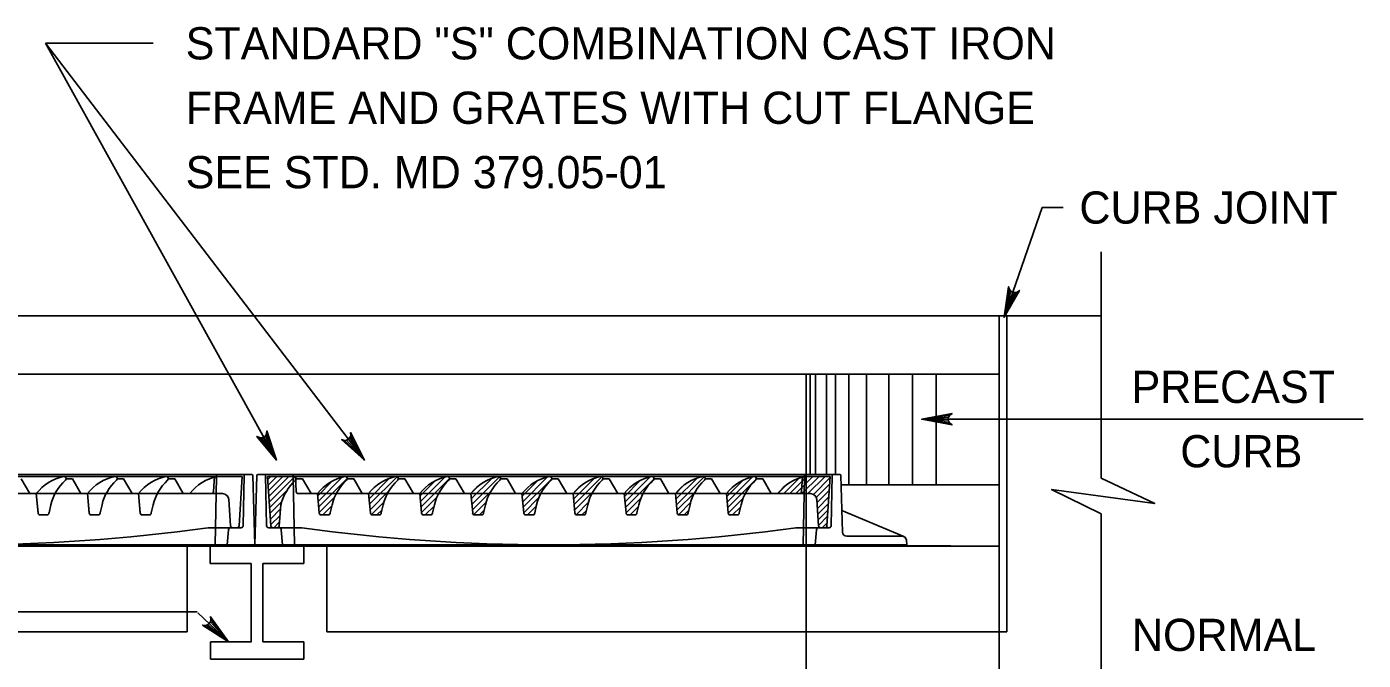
# Model space of a CAD drawing. Extents: x 2.4 to 9.7, y 1.1 to 11.2.
# Drawn here: x 7.045 to 9.535, y 9.981 to 11.161 of the extents above; entities that cross this region are included whole.
import ezdxf

# ---------------------------------------------------------------- set-up
doc = ezdxf.new("R2010")
doc.units = 0
for name, color, linetype in [('DETL-DIMS', 7, 'Continuous'), ('DETL-LINE', 7, 'Continuous'), ('DETL-NOTE', 7, 'Continuous'), ('DETL-PATT', 7, 'Continuous')]:
    doc.layers.add(name, color=color, linetype=linetype)

msp = doc.modelspace()

# ---------------------------------------------------------------- linework, layer by layer
at = {"layer": 'DETL-DIMS'}
for p, q in [((7.0801, 11.13), (7.2805, 11.13)), ((7.6745, 10.3536), (7.0801, 11.13)), ((7.0801, 11.13), (7.5105, 10.3536)), ((8.8661, 10.6198), (8.9368, 10.8241)), ((8.9368, 10.8241), (8.9761, 10.8241)), ((8.7127, 10.4299), (9.5353, 10.4299)), ((7.3624, 10.0708), (5.8534, 10.0708)), ((7.364, 10.0693), (7.4209, 10.0154))]:
    msp.add_line(p, q, dxfattribs=at)
for points in [[(8.8661, 10.6198), (8.8746, 10.6767), (8.876, 10.6716), (8.8788, 10.6682), (8.8822, 10.6664), (8.886, 10.6657), (8.8903, 10.6666), (8.8946, 10.6697), (8.8661, 10.6198), (8.8903, 10.6666), (8.886, 10.6657), (8.8661, 10.6198), (8.8822, 10.6664), (8.8788, 10.6682), (8.8661, 10.6198), (8.876, 10.6716)], [(8.7127, 10.4299), (8.7692, 10.4405), (8.7648, 10.4375), (8.7626, 10.4337), (8.7619, 10.4299), (8.7626, 10.4261), (8.7648, 10.4223), (8.7692, 10.4193), (8.7127, 10.4299), (8.7648, 10.4223), (8.7626, 10.4261), (8.7127, 10.4299), (8.7619, 10.4299), (8.7626, 10.4337), (8.7127, 10.4299), (8.7648, 10.4375)], [(7.5105, 10.3536), (7.4738, 10.3979), (7.4786, 10.3955), (7.483, 10.3954), (7.4866, 10.3967), (7.4896, 10.3991), (7.4918, 10.4029), (7.4924, 10.4081), (7.5105, 10.3536), (7.4918, 10.4029), (7.4896, 10.3991), (7.5105, 10.3536), (7.4866, 10.3967), (7.483, 10.3954), (7.5105, 10.3536), (7.4786, 10.3955)], [(7.6745, 10.3536), (7.6317, 10.392), (7.6368, 10.3904), (7.6411, 10.3909), (7.6445, 10.3927), (7.6472, 10.3955), (7.6488, 10.3996), (7.6485, 10.4049), (7.6745, 10.3536), (7.6488, 10.3996), (7.6472, 10.3955), (7.6745, 10.3536), (7.6445, 10.3927), (7.6411, 10.3909), (7.6745, 10.3536), (7.6368, 10.3904)], [(9.0468, 10.2538), (8.9546, 10.2989), (9.1468, 10.2728), (9.0468, 10.3203)], [(7.4209, 10.0154), (7.3726, 10.0465), (7.3778, 10.0457), (7.3821, 10.047), (7.3851, 10.0493), (7.3873, 10.0525), (7.3882, 10.0568), (7.3872, 10.0619), (7.4209, 10.0154), (7.3882, 10.0568), (7.3873, 10.0525), (7.4209, 10.0154), (7.3851, 10.0493), (7.3821, 10.047), (7.4209, 10.0154), (7.3778, 10.0457)]]:
    msp.add_lwpolyline(points, dxfattribs=at)
at = {"layer": 'DETL-LINE'}
for p, q in [((9.0468, 10.7416), (9.0468, 10.3203)), ((5.9539, 10.6227), (9.0468, 10.6227)), ((8.8568, 8.6227), (8.8568, 10.6227)), ((8.8713, 10.0336), (8.8713, 10.6227)), ((6.0916, 10.5136), (8.8568, 10.5136)), ((8.4972, 8.7614), (8.4972, 10.5136)), ((8.5049, 10.3269), (8.5049, 10.5136)), ((8.5148, 10.3269), (8.5148, 10.5136)), ((8.5354, 10.3269), (8.5354, 10.5136)), ((8.552, 10.3269), (8.552, 10.5136)), ((8.5766, 10.3073), (8.5766, 10.5136)), ((8.6099, 10.3073), (8.6099, 10.5136)), ((8.6512, 10.3073), (8.6512, 10.5136)), ((8.6953, 10.3073), (8.6953, 10.5136)), ((8.7395, 10.3073), (8.7395, 10.5136)), ((7.4642, 10.3269), (6.3805, 10.3269)), ((7.3947, 10.323), (7.393, 10.2949)), ((7.3967, 10.2277), (7.3986, 10.3226)), ((7.3986, 10.323), (7.3986, 10.325)), ((7.4463, 10.323), (7.4001, 10.323)), ((7.4406, 10.2314), (7.4463, 10.323)), ((7.4484, 10.2316), (7.4502, 10.325)), ((7.4502, 10.325), (7.4484, 10.2316)), ((7.4642, 10.3269), (7.4522, 10.3269)), ((7.4662, 10.325), (7.4701, 10.196)), ((7.474, 10.325), (7.4701, 10.196)), ((8.5598, 10.3269), (7.476, 10.3269)), ((7.488, 10.3269), (7.476, 10.3269)), ((7.4919, 10.2316), (7.49, 10.325)), ((7.4919, 10.2316), (7.49, 10.325)), ((7.4943, 10.3176), (7.4996, 10.323)), ((7.4949, 10.3071), (7.5108, 10.323)), ((7.4956, 10.2965), (7.522, 10.323)), ((7.4962, 10.2859), (7.5333, 10.323)), ((7.4969, 10.2754), (7.5442, 10.3227)), ((7.5416, 10.323), (7.5416, 10.325)), ((7.5435, 10.2277), (7.5416, 10.323)), ((7.5455, 10.323), (7.5472, 10.2949)), ((7.5871, 10.287), (7.6143, 10.3142)), ((7.5881, 10.2767), (7.633, 10.3216)), ((7.589, 10.2665), (7.6421, 10.3196)), ((7.6829, 10.2817), (7.7202, 10.3191)), ((7.6838, 10.2715), (7.7351, 10.3227)), ((7.7777, 10.2867), (7.8055, 10.3146)), ((7.7786, 10.2764), (7.824, 10.3218)), ((7.7796, 10.2662), (7.8327, 10.3193)), ((7.8734, 10.2814), (7.9113, 10.3192)), ((7.8744, 10.2711), (7.9258, 10.3226)), ((7.9683, 10.2864), (7.9968, 10.315)), ((7.9692, 10.2761), (8.0149, 10.3219)), ((7.9701, 10.2659), (8.0233, 10.319)), ((8.064, 10.2811), (8.1023, 10.3194)), ((8.065, 10.2708), (8.1165, 10.3224)), ((8.1588, 10.2861), (8.1881, 10.3154)), ((8.1598, 10.2758), (8.2059, 10.322)), ((8.1607, 10.2656), (8.2138, 10.3186)), ((8.2546, 10.2808), (8.2933, 10.3196)), ((8.2555, 10.2705), (8.3073, 10.3223)), ((8.3494, 10.2858), (8.3793, 10.3157)), ((8.3503, 10.2755), (8.3969, 10.3221)), ((8.3513, 10.2652), (8.4042, 10.3182)), ((8.4558, 10.2912), (8.4844, 10.3198)), ((8.4671, 10.2912), (8.4988, 10.323)), ((8.4783, 10.2912), (8.51, 10.323)), ((8.4903, 10.323), (8.4885, 10.2949)), ((8.4895, 10.2912), (8.5213, 10.323)), ((8.4923, 10.2277), (8.4941, 10.3226)), ((8.4941, 10.323), (8.4942, 10.325)), ((8.5007, 10.2912), (8.5325, 10.323)), ((8.5107, 10.2899), (8.5417, 10.321)), ((8.5439, 10.2316), (8.5458, 10.325)), ((8.5458, 10.325), (8.5439, 10.2316)), ((8.5598, 10.3269), (8.5478, 10.3269)), ((8.5617, 10.325), (8.565, 10.2195)), ((8.565, 10.2195), (8.5617, 10.325)), ((6.4556, 10.2912), (7.3367, 10.2912)), ((7.0628, 10.2912), (7.0661, 10.255)), ((7.1581, 10.2912), (7.1614, 10.255)), ((7.2533, 10.2912), (7.2566, 10.255)), ((7.3486, 10.2912), (7.4097, 10.2912)), ((7.4975, 10.2648), (7.5299, 10.2971)), ((7.5512, 10.2912), (8.4322, 10.2912)), ((7.6848, 10.2612), (7.7199, 10.2963)), ((7.8753, 10.2609), (7.91, 10.2955)), ((7.8761, 10.2953), (7.8834, 10.3026)), ((8.064, 10.2923), (8.076, 10.3044)), ((8.0659, 10.2606), (8.1001, 10.2947)), ((8.2536, 10.2911), (8.2681, 10.3056)), ((8.2565, 10.2603), (8.2902, 10.294)), ((8.4446, 10.2912), (8.4603, 10.3069)), ((8.5162, 10.2842), (8.541, 10.309)), ((8.5176, 10.2744), (8.5402, 10.297)), ((8.5623, 10.3073), (8.8568, 10.3073)), ((7.0865, 10.2552), (7.09, 10.2705)), ((7.1817, 10.2552), (7.1853, 10.2705)), ((7.277, 10.2552), (7.2806, 10.2705)), ((7.4216, 10.2801), (7.4247, 10.2314)), ((7.4982, 10.2542), (7.5204, 10.2764)), ((7.4989, 10.2437), (7.5181, 10.2629)), ((7.59, 10.2562), (7.6188, 10.285)), ((7.5965, 10.2515), (7.6136, 10.2685)), ((7.6871, 10.2522), (7.7108, 10.276)), ((7.6976, 10.2515), (7.7071, 10.261)), ((7.7805, 10.2559), (7.8091, 10.2844)), ((7.7874, 10.2515), (7.804, 10.2681)), ((7.8778, 10.2521), (7.9012, 10.2755)), ((7.8885, 10.2515), (7.8975, 10.2606)), ((7.9711, 10.2556), (7.9994, 10.2839)), ((7.9783, 10.2515), (7.9944, 10.2677)), ((8.0686, 10.252), (8.0916, 10.2751)), ((8.1616, 10.2553), (8.1897, 10.2834)), ((8.1691, 10.2515), (8.1849, 10.2672)), ((8.2593, 10.2519), (8.282, 10.2746)), ((8.3522, 10.255), (8.3801, 10.2828)), ((8.36, 10.2515), (8.3753, 10.2668)), ((8.5182, 10.2638), (8.5395, 10.2851)), ((8.5189, 10.2532), (8.5387, 10.2731)), ((8.5195, 10.2427), (8.538, 10.2611)), ((7.07, 10.2515), (7.0825, 10.2515)), ((7.1653, 10.2515), (7.1778, 10.2515)), ((7.2606, 10.2515), (7.273, 10.2515)), ((7.4995, 10.2331), (7.5171, 10.2507)), ((7.5054, 10.2277), (7.5161, 10.2384)), ((7.6082, 10.252), (7.6099, 10.2537)), ((7.7998, 10.2527), (7.7999, 10.2528)), ((8.0793, 10.2515), (8.0879, 10.2601)), ((8.2702, 10.2515), (8.2783, 10.2597)), ((8.5202, 10.2321), (8.5372, 10.2491)), ((8.527, 10.2277), (8.5365, 10.2371)), ((8.5638, 10.2595), (8.6794, 10.2111)), ((9.0468, 10.2538), (9.0468, 9.7514)), ((7.3961, 10.196), (7.3967, 10.2277)), ((7.4185, 10.196), (7.421, 10.2241)), ((7.4249, 10.2277), (7.4444, 10.2277)), ((7.4286, 10.2277), (7.4249, 10.2277)), ((7.4286, 10.2277), (7.4366, 10.2277)), ((7.4444, 10.2277), (7.4287, 10.2277)), ((7.5153, 10.2277), (7.4958, 10.2277)), ((7.5217, 10.196), (7.5193, 10.2241)), ((7.5441, 10.196), (7.5435, 10.2277)), ((8.4917, 10.196), (8.4923, 10.2277)), ((8.5141, 10.196), (8.5165, 10.2241)), ((8.5205, 10.2277), (8.54, 10.2277)), ((8.5241, 10.2277), (8.5205, 10.2277)), ((8.54, 10.2277), (8.5243, 10.2277)), ((8.5729, 10.2118), (8.6761, 10.2118)), ((8.6761, 10.2118), (8.5729, 10.2118)), ((8.6794, 10.2111), (8.6789, 10.2113)), ((7.4701, 10.196), (6.2555, 10.196)), ((6.3638, 10.1936), (8.8568, 10.1936)), ((7.3439, 10.0336), (7.3439, 10.1936)), ((7.3868, 10.1609), (7.3868, 10.1936)), ((8.6848, 10.196), (7.4701, 10.196)), ((7.5614, 10.1609), (7.5614, 10.1936)), ((7.6043, 10.0336), (7.6043, 10.1936)), ((8.6848, 10.196), (8.684, 10.2046)), ((7.3868, 10.1609), (7.4633, 10.1609)), ((7.4633, 10.1609), (7.4633, 10.0154)), ((7.4851, 10.1609), (7.4851, 10.0154)), ((7.4851, 10.1609), (7.5614, 10.1609)), ((6.4511, 10.0336), (7.3439, 10.0336)), ((7.3873, 9.9827), (7.3873, 10.0154)), ((7.3873, 10.0154), (7.4635, 10.0154)), ((7.4851, 10.0154), (7.5614, 10.0154)), ((7.5614, 9.9827), (7.5614, 10.0154)), ((7.5614, 10.015), (7.5614, 10.0154)), ((7.6043, 10.0336), (8.4972, 10.0336)), ((8.4972, 10.0336), (8.8568, 10.0336)), ((8.8713, 10.0336), (8.8568, 10.0336)), ((7.3873, 9.9827), (7.5614, 9.9827))]:
    msp.add_line(p, q, dxfattribs=at)
for points in [[(7.421, 10.2241), (7.4185, 10.196), (7.4701, 10.196), (7.4662, 10.325)], [(7.474, 10.325), (7.4701, 10.196), (7.5217, 10.196), (7.5193, 10.2241)], [(7.5153, 10.2277), (7.5115, 10.2277), (7.5036, 10.2277), (7.4958, 10.2277)], [(8.5165, 10.2241), (8.5141, 10.196), (8.6848, 10.196), (8.684, 10.2046)]]:
    msp.add_lwpolyline(points, dxfattribs=at)
for centre, radius, start, end in [((7.1323, 10.2362), 0.0887, 101.6847, 141.6027), ((7.1764, 10.2502), 0.0887, 132.0547, 166.7971), ((7.1143, 10.319), 0.00397, 312.139, 90), ((7.2275, 10.2362), 0.0887, 101.6847, 141.6027), ((7.2716, 10.2502), 0.0887, 132.0547, 166.7971), ((7.2096, 10.319), 0.00397, 312.139, 90), ((7.3228, 10.2362), 0.0887, 101.6847, 141.6027), ((7.3669, 10.2502), 0.0887, 132.0547, 166.7971), ((7.3049, 10.319), 0.00397, 312.139, 90), ((7.4181, 10.2362), 0.0887, 101.6847, 141.6027), ((7.4006, 10.325), 0.00198, 90, 178.8778), ((7.4522, 10.325), 0.00198, 90, 178.8542), ((7.4522, 10.325), 0.00198, 90, 178.8542), ((7.4642, 10.325), 0.00198, 1.7855, 90), ((7.4642, 10.325), 0.00198, 1.7855, 90), ((7.476, 10.325), 0.00198, 90, 178.2145), ((7.476, 10.325), 0.00198, 90, 178.2145), ((7.488, 10.325), 0.00198, 1.1458, 90), ((7.488, 10.325), 0.00198, 1.1458, 90), ((7.5396, 10.325), 0.00198, 1.1222, 90), ((8.4962, 10.325), 0.00198, 90, 178.8778), ((8.5478, 10.325), 0.00198, 90, 178.8542), ((8.5478, 10.325), 0.00198, 90, 178.8542), ((8.5598, 10.325), 0.00198, 1.7855, 90), ((8.5598, 10.325), 0.00198, 1.7855, 90), ((7.389, 10.2952), 0.00397, 269.9993, 356.4126), ((7.4097, 10.2793), 0.0119, 3.5763, 89.9993), ((7.5512, 10.2952), 0.00397, 183.5874, 270.0007), ((8.4846, 10.2952), 0.00397, 269.9993, 356.4126), ((7.07, 10.2555), 0.00397, 186.5049, 270), ((7.0825, 10.2555), 0.00397, 270, 356.0265), ((7.1653, 10.2555), 0.00397, 186.5049, 270), ((7.1778, 10.2555), 0.00397, 270, 356.0265), ((7.2606, 10.2555), 0.00397, 186.5049, 270), ((7.273, 10.2555), 0.00397, 270, 356.0265), ((7.4249, 10.2237), 0.00397, 90, 175), ((7.4249, 10.2237), 0.00397, 90, 175), ((7.4286, 10.2317), 0.00397, 183.5763, 268.8729), ((7.4286, 10.2317), 0.00397, 268.8729, 271.1271), ((7.4366, 10.2317), 0.00397, 270, 356.4126), ((7.4444, 10.2317), 0.00397, 270, 358.8542), ((7.4444, 10.2317), 0.00397, 270, 358.8542), ((7.4958, 10.2317), 0.00397, 181.1458, 270), ((7.4958, 10.2317), 0.00397, 181.1458, 270), ((7.5153, 10.2237), 0.00397, 5, 90), ((7.5153, 10.2237), 0.00397, 5, 90), ((8.5205, 10.2237), 0.00397, 90, 175), ((8.5205, 10.2237), 0.00397, 90, 175), ((8.5242, 10.2317), 0.00397, 268.8729, 271.1271), ((8.54, 10.2317), 0.00397, 270, 358.8542), ((8.54, 10.2317), 0.00397, 270, 358.8542), ((8.5729, 10.2198), 0.00794, 181.7416, 270), ((8.5729, 10.2198), 0.00794, 181.7416, 270), ((8.6761, 10.2039), 0.00794, 5, 90), ((8.6761, 10.2039), 0.00794, 69.5728, 90), ((8.6761, 10.2039), 0.00794, 5, 65.0296)]:
    msp.add_arc(centre, radius, start, end, dxfattribs=at)
at = {"layer": 'DETL-NOTE'}
for p, q in [((7.4463, 10.323), (6.3984, 10.323)), ((7.0509, 10.2912), (7.0349, 10.319)), ((7.1183, 10.319), (7.1302, 10.319)), ((7.1461, 10.2912), (7.1302, 10.319)), ((7.2136, 10.319), (7.2255, 10.319)), ((7.2414, 10.2912), (7.2255, 10.319)), ((7.3088, 10.319), (7.3207, 10.319)), ((7.3367, 10.2912), (7.3207, 10.319)), ((7.4463, 10.323), (7.4406, 10.2314)), ((7.4463, 10.323), (7.4463, 10.323)), ((7.4503, 10.3269), (7.4503, 10.3269)), ((7.4741, 10.3269), (7.4741, 10.3269)), ((7.49, 10.3269), (7.49, 10.3269)), ((8.5419, 10.323), (7.4939, 10.323)), ((7.4939, 10.323), (7.4996, 10.2314)), ((7.547, 10.319), (7.5589, 10.319)), ((7.5748, 10.2912), (7.5589, 10.319)), ((7.6423, 10.319), (7.6542, 10.319)), ((7.6701, 10.2912), (7.6542, 10.319)), ((7.7375, 10.319), (7.7494, 10.319)), ((7.7654, 10.2912), (7.7494, 10.319)), ((7.8328, 10.319), (7.8447, 10.319)), ((7.8606, 10.2912), (7.8447, 10.319)), ((7.9281, 10.319), (7.94, 10.319)), ((7.9559, 10.2912), (7.94, 10.319)), ((8.0233, 10.319), (8.0352, 10.319)), ((8.0512, 10.2912), (8.0352, 10.319)), ((8.1186, 10.319), (8.1305, 10.319)), ((8.1464, 10.2912), (8.1305, 10.319)), ((8.2139, 10.319), (8.2258, 10.319)), ((8.2417, 10.2912), (8.2258, 10.319)), ((8.3091, 10.319), (8.321, 10.319)), ((8.337, 10.2912), (8.321, 10.319)), ((8.4044, 10.319), (8.4163, 10.319)), ((8.4322, 10.2912), (8.4163, 10.319)), ((8.5419, 10.323), (8.5361, 10.2314)), ((8.5419, 10.323), (8.5419, 10.323)), ((8.5458, 10.3269), (8.5458, 10.3269)), ((8.5578, 10.3269), (8.5578, 10.3269)), ((8.5617, 10.3269), (8.5617, 10.3269)), ((7.0628, 10.2912), (7.0509, 10.2912)), ((7.0628, 10.2912), (7.0661, 10.2552)), ((7.1581, 10.2912), (7.1461, 10.2912)), ((7.1581, 10.2912), (7.1614, 10.2552)), ((7.2533, 10.2912), (7.2414, 10.2912)), ((7.2533, 10.2912), (7.2566, 10.2552)), ((7.3486, 10.2912), (7.3367, 10.2912)), ((7.4097, 10.2912), (7.3486, 10.2912)), ((7.5868, 10.2912), (7.5748, 10.2912)), ((7.5868, 10.2912), (7.5901, 10.2552)), ((7.682, 10.2912), (7.6701, 10.2912)), ((7.682, 10.2912), (7.6853, 10.2552)), ((7.7773, 10.2912), (7.7654, 10.2912)), ((7.7773, 10.2912), (7.7806, 10.2552)), ((7.8726, 10.2912), (7.8606, 10.2912)), ((7.8726, 10.2912), (7.8759, 10.2552)), ((7.9678, 10.2912), (7.9559, 10.2912)), ((7.9678, 10.2912), (7.9711, 10.2552)), ((8.0631, 10.2912), (8.0512, 10.2912)), ((8.0631, 10.2912), (8.0664, 10.2552)), ((8.1584, 10.2912), (8.1464, 10.2912)), ((8.1584, 10.2912), (8.1617, 10.2552)), ((8.2536, 10.2912), (8.2417, 10.2912)), ((8.2536, 10.2912), (8.2569, 10.2552)), ((8.3489, 10.2912), (8.337, 10.2912)), ((8.3489, 10.2912), (8.3522, 10.2552)), ((8.4442, 10.2912), (8.4322, 10.2912)), ((8.5053, 10.2912), (8.4442, 10.2912)), ((8.5053, 10.2912), (8.5053, 10.2912)), ((7.0865, 10.2552), (7.09, 10.2705)), ((7.1817, 10.2552), (7.1853, 10.2705)), ((7.277, 10.2552), (7.2806, 10.2705)), ((7.4216, 10.2801), (7.4247, 10.2314)), ((7.5187, 10.2705), (7.5155, 10.2314)), ((7.6104, 10.2552), (7.614, 10.2705)), ((7.7057, 10.2552), (7.7093, 10.2705)), ((7.801, 10.2552), (7.8045, 10.2705)), ((7.8962, 10.2552), (7.8998, 10.2705)), ((7.9915, 10.2552), (7.9951, 10.2705)), ((8.0868, 10.2552), (8.0903, 10.2705)), ((8.182, 10.2552), (8.1856, 10.2705)), ((8.2773, 10.2552), (8.2809, 10.2705)), ((8.3726, 10.2552), (8.3761, 10.2705)), ((8.5172, 10.2801), (8.5202, 10.2314)), ((7.0825, 10.2515), (7.07, 10.2515)), ((7.1778, 10.2515), (7.1653, 10.2515)), ((7.273, 10.2515), (7.2606, 10.2515)), ((7.6065, 10.2515), (7.594, 10.2515)), ((7.7017, 10.2515), (7.6893, 10.2515)), ((7.797, 10.2515), (7.7845, 10.2515)), ((7.8923, 10.2515), (7.8798, 10.2515)), ((7.9875, 10.2515), (7.9751, 10.2515)), ((8.0828, 10.2515), (8.0703, 10.2515)), ((8.1781, 10.2515), (8.1656, 10.2515)), ((8.2733, 10.2515), (8.2609, 10.2515)), ((8.3686, 10.2515), (8.3561, 10.2515)), ((8.3686, 10.2515), (8.3686, 10.2515)), ((7.4286, 10.2277), (7.3828, 10.2277)), ((7.4366, 10.2277), (7.4286, 10.2277)), ((7.5115, 10.2277), (7.5036, 10.2277)), ((7.5574, 10.2277), (7.5115, 10.2277)), ((8.5241, 10.2277), (8.4783, 10.2277)), ((8.5322, 10.2277), (8.5241, 10.2277)), ((8.5322, 10.2277), (8.5322, 10.2277)), ((8.54, 10.2277), (8.54, 10.2277)), ((7.4185, 10.196), (7.4185, 10.196)), ((7.4701, 10.196), (7.4701, 10.196)), ((7.5217, 10.196), (7.5217, 10.196)), ((8.5141, 10.196), (8.5141, 10.196)), ((8.6848, 10.196), (8.6848, 10.196))]:
    msp.add_line(p, q, dxfattribs=at)
for centre, radius, start, end in [((7.1323, 10.2362), 0.0887, 101.6847, 141.6027), ((7.1764, 10.2502), 0.0887, 132.0547, 166.7971), ((7.1143, 10.319), 0.00397, 312.139, 90), ((7.2275, 10.2362), 0.0887, 101.6847, 141.6027), ((7.2716, 10.2502), 0.0887, 132.0547, 166.7971), ((7.2096, 10.319), 0.00397, 312.139, 90), ((7.3228, 10.2362), 0.0887, 101.6847, 141.6027), ((7.3669, 10.2502), 0.0887, 132.0547, 166.7971), ((7.3049, 10.319), 0.00397, 312.139, 90), ((7.4181, 10.2362), 0.0887, 101.6847, 141.6027), ((7.6051, 10.2502), 0.0887, 132.0547, 166.7971), ((7.543, 10.319), 0.00397, 312.139, 90), ((7.6562, 10.2362), 0.0887, 101.6847, 141.6027), ((7.7003, 10.2502), 0.0887, 132.0547, 166.7971), ((7.6383, 10.319), 0.00397, 312.139, 90), ((7.7515, 10.2362), 0.0887, 101.6847, 141.6027), ((7.7956, 10.2502), 0.0887, 132.0547, 166.7971), ((7.7335, 10.319), 0.00397, 312.139, 90), ((7.8468, 10.2362), 0.0887, 101.6847, 141.6027), ((7.8909, 10.2502), 0.0887, 132.0547, 166.7971), ((7.8288, 10.319), 0.00397, 312.139, 90), ((7.942, 10.2362), 0.0887, 101.6847, 141.6027), ((7.9861, 10.2502), 0.0887, 132.0547, 166.7971), ((7.9241, 10.319), 0.00397, 312.139, 90), ((8.0373, 10.2362), 0.0887, 101.6847, 141.6027), ((8.0814, 10.2502), 0.0887, 132.0547, 166.7971), ((8.0193, 10.319), 0.00397, 312.139, 90), ((8.1326, 10.2362), 0.0887, 101.6847, 141.6027), ((8.1767, 10.2502), 0.0887, 132.0547, 166.7971), ((8.1146, 10.319), 0.00397, 312.139, 90), ((8.2278, 10.2362), 0.0887, 101.6847, 141.6027), ((8.2719, 10.2502), 0.0887, 132.0547, 166.7971), ((8.2099, 10.319), 0.00397, 312.139, 90), ((8.3231, 10.2362), 0.0887, 101.6847, 141.6027), ((8.3672, 10.2502), 0.0887, 132.0547, 166.7971), ((8.3051, 10.319), 0.00397, 312.139, 90), ((8.4184, 10.2362), 0.0887, 101.6847, 141.6027), ((8.4625, 10.2502), 0.0887, 132.0547, 166.7971), ((8.4004, 10.319), 0.00397, 312.139, 90), ((8.5136, 10.2362), 0.0887, 101.6847, 141.6027), ((7.4097, 10.2793), 0.0119, 3.5763, 90), ((8.5053, 10.2793), 0.0119, 3.5763, 90), ((7.07, 10.2555), 0.00397, 183.9735, 270), ((7.0825, 10.2555), 0.00397, 270, 356.0265), ((7.1653, 10.2555), 0.00397, 183.9735, 270), ((7.1778, 10.2555), 0.00397, 270, 356.0265), ((7.2606, 10.2555), 0.00397, 183.9735, 270), ((7.273, 10.2555), 0.00397, 270, 356.0265), ((7.594, 10.2555), 0.00397, 183.9735, 270), ((7.6065, 10.2555), 0.00397, 270, 356.0265), ((7.6893, 10.2555), 0.00397, 183.9735, 270), ((7.7017, 10.2555), 0.00397, 270, 356.0265), ((7.7845, 10.2555), 0.00397, 183.9735, 270), ((7.797, 10.2555), 0.00397, 270, 356.0265), ((7.8798, 10.2555), 0.00397, 183.9735, 270), ((7.8923, 10.2555), 0.00397, 270, 356.0265), ((7.9751, 10.2555), 0.00397, 183.9735, 270), ((7.9875, 10.2555), 0.00397, 270, 356.0265), ((8.0703, 10.2555), 0.00397, 183.9735, 270), ((8.0828, 10.2555), 0.00397, 270, 356.0265), ((8.1656, 10.2555), 0.00397, 183.9735, 270), ((8.1781, 10.2555), 0.00397, 270, 356.0265), ((8.2609, 10.2555), 0.00397, 183.9735, 270), ((8.2733, 10.2555), 0.00397, 270, 356.0265), ((8.3561, 10.2555), 0.00397, 183.9735, 270), ((8.3686, 10.2555), 0.00397, 270, 356.0265), ((6.9223, 13.5501), 3.3542, 262.1096, 277.8904), ((7.4286, 10.2317), 0.00397, 183.5763, 270), ((7.4366, 10.2317), 0.00397, 270, 356.4126), ((7.5036, 10.2317), 0.00397, 183.5616, 270), ((7.5115, 10.2317), 0.00397, 270, 355.2441), ((8.0179, 13.5501), 3.3542, 262.1096, 277.8904), ((8.5242, 10.2317), 0.00397, 183.5763, 270), ((8.5322, 10.2317), 0.00397, 270, 356.4126)]:
    msp.add_arc(centre, radius, start, end, dxfattribs=at)
at = {"layer": 'DETL-PATT'}
msp.add_lwpolyline([(6.0916, 8.8462), (6.4511, 8.8462), (6.4511, 8.7614), (8.4972, 8.7614), (8.4972, 10.196), (8.8568, 10.1936), (8.8568, 8.6227), (6.0916, 8.6227)], close=True, dxfattribs=at)

# ---------------------------------------------------------------- texts
at = {"layer": 'DETL-NOTE'}
for s, p in [('STANDARD "S" COMBINATION CAST IRON', (7.3411, 11.1)), ('FRAME AND GRATES WITH CUT FLANGE', (7.3411, 10.98)), ('SEE STD. MD 379.05-01', (7.3411, 10.86)), ('CURB JOINT', (9.0064, 10.7941)), ('PRECAST', (9.1036, 10.4602)), ('CURB', (9.1944, 10.3402)), ('NORMAL', (9.1043, 9.9981))]:
    msp.add_text(s, height=0.06, dxfattribs=at).set_placement(p)

doc.saveas('drawing.dxf')
